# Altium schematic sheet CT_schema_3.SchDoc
size 321 x 302 mm
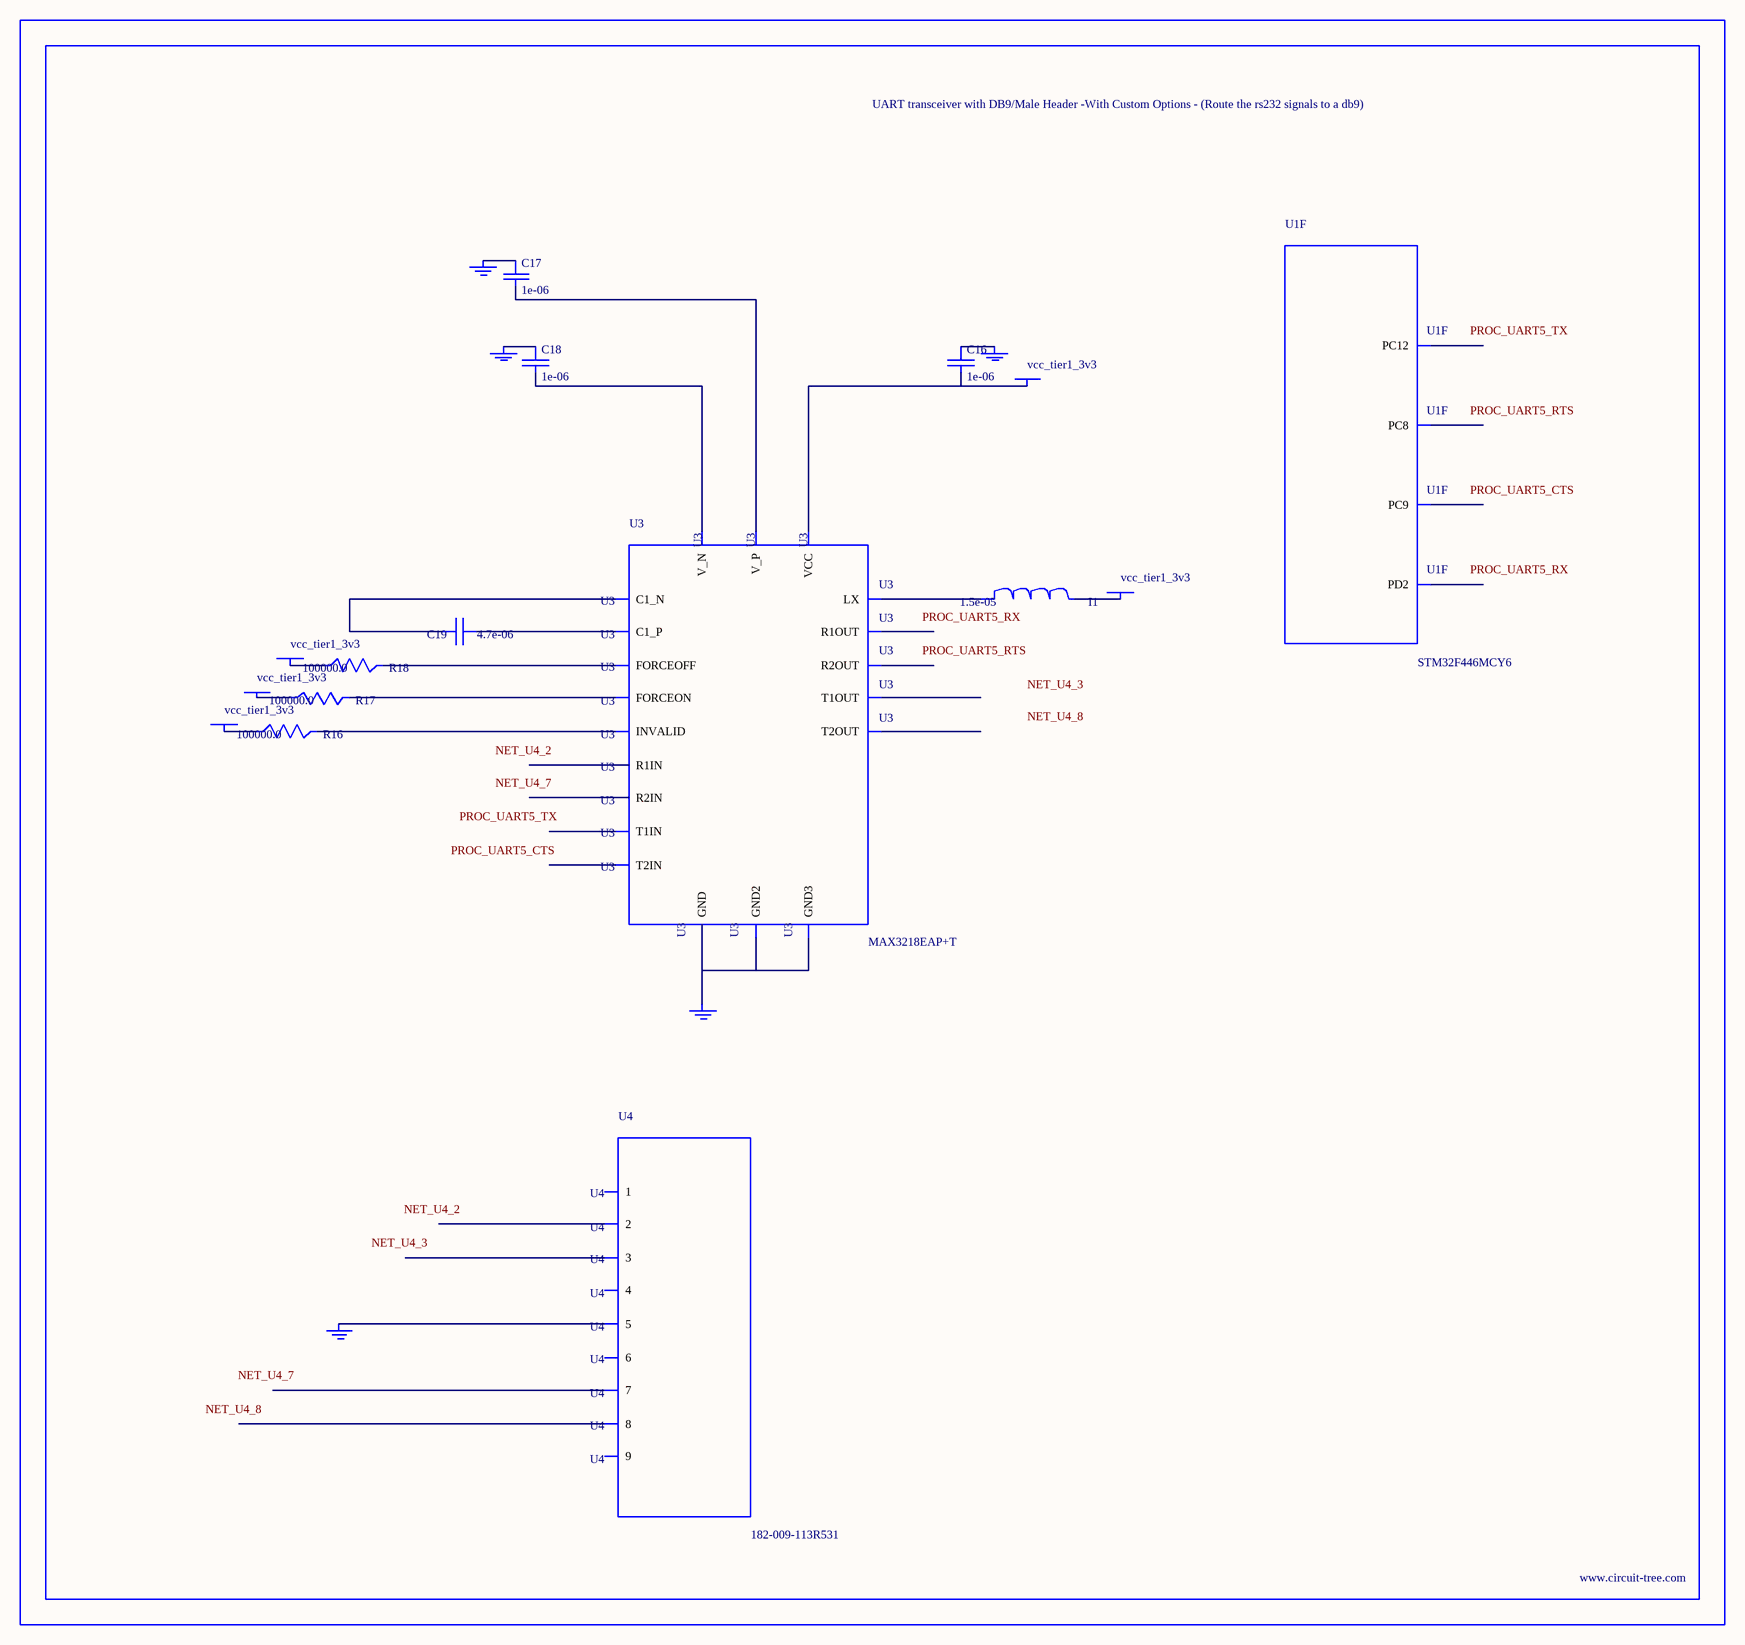
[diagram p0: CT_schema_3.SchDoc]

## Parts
BORDER2  (no value)
C16  1e-06  [C0603]
C17  1e-06  [C0603]
C18  1e-06  [C0603]
C19  4.7e-06  [C0805]
GND_INSTANCE_2_0  (no value)
GND_INSTANCE_2_1  (no value)
GND_INSTANCE_2_2  (no value)
GND_INSTANCE_2_3  (no value)
GND_INSTANCE_2_4  (no value)
I1  1.5e-05  [L1210]
POWER_INSTANCE_2_0  vcc_tier1_3v3
POWER_INSTANCE_2_1  vcc_tier1_3v3
POWER_INSTANCE_2_2  vcc_tier1_3v3
POWER_INSTANCE_2_3  vcc_tier1_3v3
POWER_INSTANCE_2_4  vcc_tier1_3v3
R16  100000.0  [R0603]
R17  100000.0  [R0603]
R18  100000.0  [R0603]
U1  STM32F446MCY6  [WLCSP81]  (part F of 9)
U3  MAX3218EAP+T  [SSOP-20]
U4  182-009-113R531  [182-009-MALE]

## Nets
NetC16_1: C16.1 GND_INSTANCE_2_0.0(GND)
NetC16_2: C16.2 POWER_INSTANCE_2_4.0(PWR) U3.6(VCC)
NetC17_1: C17.1 GND_INSTANCE_2_2.0(GND)
NetC17_2: C17.2 U3.19(V_P)
NetC18_1: C18.1 GND_INSTANCE_2_1.0(GND)
NetC18_2: C18.2 U3.15(V_N)
NetC19_1: C19.1 U3.18(C1_P)
NetC19_2: C19.2 U3.16(C1_N)
NetGND_INSTANCE_2_3_0: GND_INSTANCE_2_3.0(GND) U3.5(GND) U3.17(GND2) U3.20(GND3)
NetGND_INSTANCE_2_4_0: GND_INSTANCE_2_4.0(GND) U4.5
NetI1_1: I1.1 U3.1(LX)
NetI1_2: I1.2 POWER_INSTANCE_2_0.0(PWR)
NetPOWER_INSTANCE_2_1_0: POWER_INSTANCE_2_1.0(PWR) R16.1
NetPOWER_INSTANCE_2_2_0: POWER_INSTANCE_2_2.0(PWR) R17.1
NetPOWER_INSTANCE_2_3_0: POWER_INSTANCE_2_3.0(PWR) R18.1
NetR16_2: R16.2 U3.2(INVALID)
NetR17_2: R17.2 U3.3(FORCEON)
NetR18_2: R18.2 U3.4(FORCEOFF)

Not connected (* = marked no-connect by the designer): U1 A2(PC12) D1(PC9) D5(PD2) F3(PC8); U3 7(T1IN) 8(T2IN) 9(R1OUT) 10(R2OUT) 11(R2IN) 12(R1IN) 13(T2OUT) 14(T1OUT); U4 1 2 3 4 6 7 8 9

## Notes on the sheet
- Labels drawn without touching a wire or pin: NET_U4_2, NET_U4_3, NET_U4_7, NET_U4_8, PROC_UART5_CTS, PROC_UART5_RTS, PROC_UART5_RX, PROC_UART5_TX

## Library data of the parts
BORDER2 = BORDER_PAGE2
C16-C18 = C0603C105K3RACTU
C19 = C0805C475K4RACTU
GND_INSTANCE_2_0-GND_INSTANCE_2_4 = GND
I1 = L1210R150MDWIT
POWER_INSTANCE_2_0-POWER_INSTANCE_2_4 = PWR
R16-R18 = RC0603JR-07100KL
